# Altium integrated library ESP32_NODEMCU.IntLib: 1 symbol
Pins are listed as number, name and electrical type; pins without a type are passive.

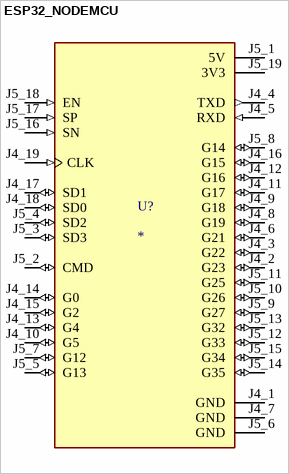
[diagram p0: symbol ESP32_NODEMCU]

## ESP32_NODEMCU
designator U?
NodeMCU is an open source loT platform. ESP32 is a series of low cost, low powersystem-on-chip (SoC) microcontrollers with integrated Wi-Fi & dual-mode Bluetooth.; MF: Espressif Systems; MP: ESP32 NodeMCU
footprint MODULE_ESP32_NODEMCU
pins: J4_1 GND (power), J4_2 G23 (io), J4_3 G22 (io), J4_4 TXD (out), J4_5 RXD (in), J4_6 G21 (io), J4_7 GND (power), J4_8 G19 (io), J4_9 G18 (io), J4_10 G5 (io), J4_11 G17 (io), J4_12 G16 (io), J4_13 G4 (io), J4_14 G0 (io), J4_15 G2 (io), J4_16 G15 (io), J4_17 SD1 (io), J4_18 SD0 (io), J4_19 CLK (in), J5_1 5V (power), J5_2 CMD (io), J5_3 SD3 (io), J5_4 SD2 (io), J5_5 G13 (io), J5_6 GND (power), J5_7 G12 (io), J5_8 G14 (io), J5_9 G27 (io), J5_10 G26 (io), J5_11 G25 (io), J5_12 G33 (io), J5_13 G32 (io), J5_14 G35 (io), J5_15 G34 (io), J5_16 SN (in), J5_17 SP (in), J5_18 EN (in), J5_19 3V3 (power)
